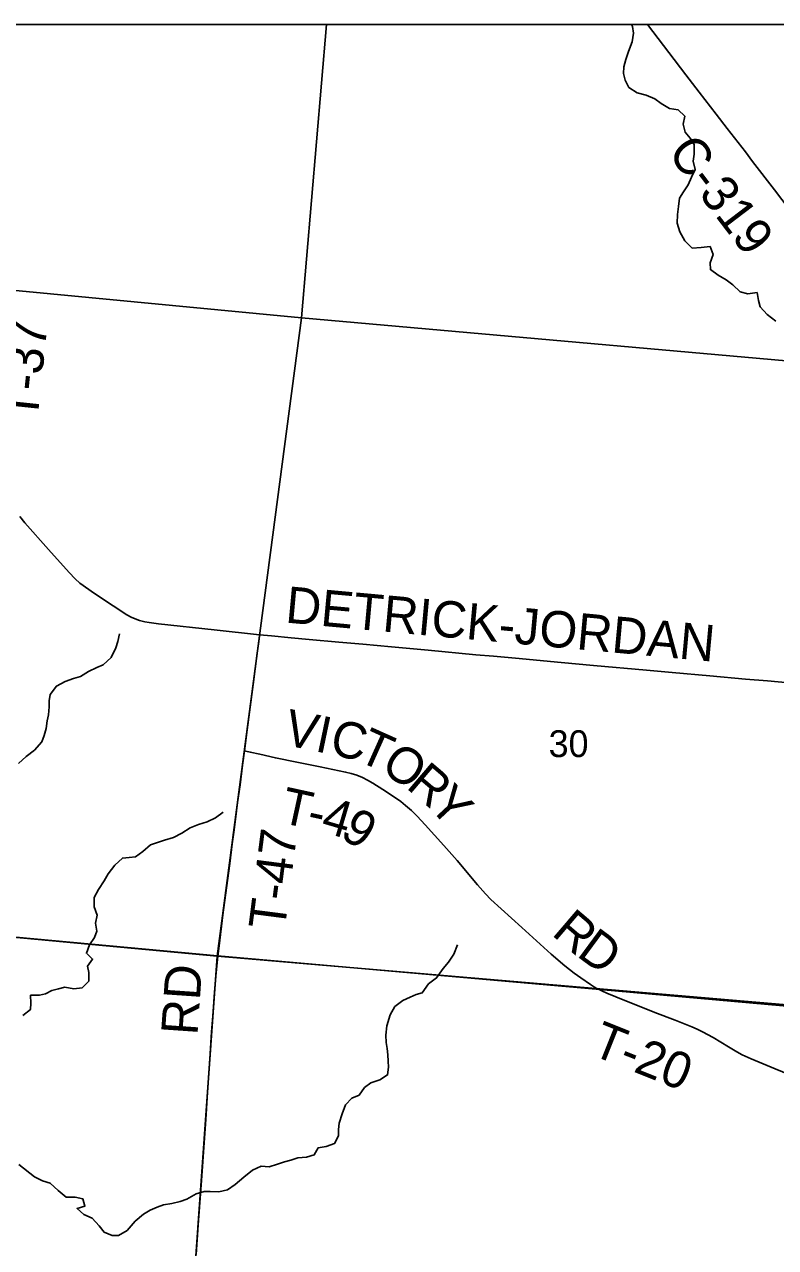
# Model space of a CAD drawing. Extents: x 0 to 34, y 0 to 22.
# Drawn here: x 3.909 to 5.08, y 18.991 to 20.9 of the extents above; entities that cross this region are included whole.
import ezdxf

# ---------------------------------------------------------------- set-up
doc = ezdxf.new("R2010")
doc.units = 0
for name, color, linetype in [('Default', 7, 'Continuous'), ('GM_X_City_Street', 7, 'Continuous'), ('GM_X_County_Road', 7, 'Continuous'), ('GM_X_County_Road_Text', 7, 'Continuous'), ('GM_X_Minor_River', 7, 'Continuous'), ('GM_X_Section', 7, 'Continuous'), ('GM_X_Section_Text', 7, 'Continuous'), ('GM_X_Township_Road', 7, 'Continuous'), ('GM_X_Township_Road_Text', 7, 'Continuous')]:
    doc.layers.add(name, color=color, linetype=linetype)

msp = doc.modelspace()

# ---------------------------------------------------------------- linework, layer by layer
at = {"layer": 'Default'}
for points in [[(4.3798, 20.9), (3.3925, 20.9), (3.3559, 20.5363), (4.3405, 20.4419)], [(5.3633, 20.9), (4.3798, 20.9), (4.3405, 20.4419), (5.3135, 20.3557)]]:
    msp.add_lwpolyline(points, close=True, dxfattribs=at)
at = {"layer": 'GM_X_City_Street'}
for points in [[(8.7795, 20.9), (3.3961, 20.9)], [(5.185, 18.9419), (5.1894, 18.9945), (5.1927, 19.0376), (5.1954, 19.0684), (5.2004, 19.1272), (5.2034, 19.1643), (5.2042, 19.1724), (5.2077, 19.2098), (5.2093, 19.2272), (5.2108, 19.2453), (5.2133, 19.2734), (5.2164, 19.3114), (5.2191, 19.3417), (5.2204, 19.3568), (4.8058, 19.3935), (4.2098, 19.4463), (3.2709, 19.533)], [(3.2709, 19.533), (4.2098, 19.4463), (4.8058, 19.3935), (5.2204, 19.3568), (5.9589, 19.2964), (6.8431, 19.2142)]]:
    msp.add_lwpolyline(points, dxfattribs=at)
at = {"layer": 'GM_X_County_Road'}
for points in [[(5.2974, 20.3579), (5.293, 20.3644), (5.2855, 20.3743), (5.2601, 20.4057), (5.2427, 20.4276), (5.2294, 20.4448), (5.2049, 20.4768), (5.1878, 20.4989), (5.1537, 20.5432), (5.1404, 20.5604), (5.1177, 20.5899), (5.1065, 20.6047), (5.0895, 20.627), (5.0782, 20.6418), (5.0442, 20.6861), (5.0329, 20.7009), (5.0045, 20.7378), (4.9874, 20.76), (4.9609, 20.7944), (4.9401, 20.8215), (4.9136, 20.856), (4.8967, 20.8782), (4.88, 20.9)], [(3.9011, 20.1318), (3.9091, 20.1223), (3.9462, 20.0804), (3.9782, 20.0446), (3.9878, 20.0346), (3.995, 20.0281), (3.9999, 20.0242), (4.0125, 20.0152), (4.027, 20.0056), (4.047, 19.9924), (4.0681, 19.9787), (4.0748, 19.975), (4.0813, 19.9721), (4.0877, 19.9697), (4.0963, 19.9676), (4.1031, 19.9663), (4.1177, 19.9644), (4.2042, 19.9551), (4.2753, 19.9475)], [(4.2753, 19.9475), (4.2937, 19.9455), (4.3247, 19.9425), (4.3525, 19.9399), (4.3989, 19.9359), (4.4361, 19.9328), (4.4807, 19.9284), (4.5381, 19.9233), (4.6124, 19.9163), (4.6402, 19.914), (4.6742, 19.9108), (4.7454, 19.9041), (4.7958, 19.8994), (4.8784, 19.892), (4.9186, 19.8883), (4.9774, 19.8831), (5.0331, 19.8781), (5.0672, 19.8753), (5.1228, 19.8701), (5.1909, 19.864), (5.231, 19.8603), (5.2642, 19.8573)]]:
    msp.add_lwpolyline(points, dxfattribs=at)
at = {"layer": 'GM_X_Minor_River'}
for points in [[(5.0802, 20.4367), (5.067, 20.4475), (5.0558, 20.4594), (5.0536, 20.4689), (5.0511, 20.4815), (5.0367, 20.4797), (5.0246, 20.4825), (5.0133, 20.4937), (5.0031, 20.5014), (4.9903, 20.5088), (4.9783, 20.5173), (4.978, 20.5279), (4.9827, 20.5411), (4.9779, 20.5533), (4.9639, 20.5516), (4.9498, 20.551), (4.9386, 20.5625), (4.9304, 20.5763), (4.9267, 20.5896), (4.9269, 20.6033), (4.9286, 20.6158), (4.9299, 20.6287), (4.9365, 20.6385), (4.9438, 20.6498), (4.9489, 20.6615), (4.9544, 20.6736), (4.9515, 20.6866), (4.9531, 20.6975), (4.9529, 20.7124), (4.9466, 20.7223), (4.9391, 20.7319), (4.9359, 20.7444), (4.9387, 20.7566), (4.9278, 20.7669), (4.9145, 20.7686), (4.9017, 20.7767), (4.8915, 20.7841), (4.8779, 20.7896), (4.8639, 20.7935), (4.8511, 20.8016), (4.8452, 20.8131), (4.843, 20.8234), (4.8431, 20.834), (4.8463, 20.8454), (4.8506, 20.8578), (4.8561, 20.873), (4.8586, 20.8866), (4.8568, 20.8969), (4.8553, 20.9)], [(3.899, 19.7467), (3.9113, 19.7576), (3.9243, 19.7673), (3.9355, 19.7804), (3.9394, 19.7903), (3.9422, 19.8009), (3.9439, 19.813), (3.9459, 19.8225), (3.9468, 19.835), (3.947, 19.8445), (3.9486, 19.8544), (3.9582, 19.8672), (3.972, 19.8746), (3.985, 19.879), (3.9957, 19.8823), (4.0083, 19.8898), (4.0213, 19.8961), (4.0312, 19.9005), (4.0435, 19.9121), (4.0509, 19.9269), (4.0541, 19.9367), (4.0569, 19.9488)], [(3.9058, 19.3533), (3.9177, 19.3623), (3.9186, 19.3726), (3.918, 19.3847), (3.9317, 19.3849), (3.9412, 19.3871), (3.9512, 19.3923), (3.9618, 19.3948), (3.9714, 19.3974), (3.9854, 19.3949), (3.9983, 19.3963), (4.0087, 19.4068), (4.0089, 19.4205), (4.0067, 19.43), (4.0148, 19.4413), (4.0051, 19.4502), (4.0098, 19.4634), (4.0179, 19.4751), (4.0215, 19.485), (4.0193, 19.4975), (4.0218, 19.51), (4.017, 19.523), (4.0172, 19.5371), (4.0242, 19.5499), (4.0327, 19.5631), (4.0389, 19.5744), (4.0493, 19.5876), (4.0613, 19.5989), (4.0719, 19.5995), (4.0814, 19.6009), (4.0933, 19.6091), (4.1048, 19.6196), (4.1144, 19.6226), (4.1269, 19.6266), (4.141, 19.631), (4.154, 19.6377), (4.1667, 19.6459), (4.18, 19.6511), (4.1934, 19.6555), (4.2064, 19.6618), (4.2183, 19.6704)], [(3.8999, 19.1204), (3.9243, 19.1011), (3.9364, 19.0953), (3.9485, 19.0913), (3.9609, 19.0798), (3.9737, 19.0697), (3.9874, 19.0696), (3.9995, 19.0672), (4.0028, 19.0557), (3.9905, 19.0517), (4.0011, 19.0428), (4.0143, 19.037), (4.0248, 19.0251), (4.0326, 19.0151), (4.0455, 19.01), (4.0554, 19.0099), (4.0687, 19.0177), (4.0811, 19.032), (4.0941, 19.0429), (4.1045, 19.0492), (4.1152, 19.054), (4.1251, 19.0577), (4.1384, 19.0598), (4.1514, 19.0627), (4.1617, 19.0664), (4.1762, 19.0746), (4.1888, 19.0782), (4.1983, 19.0785), (4.2116, 19.078), (4.2253, 19.0812), (4.2372, 19.0894), (4.2506, 19.1007), (4.2644, 19.1115), (4.2774, 19.1178), (4.2899, 19.1169), (4.3033, 19.121), (4.314, 19.125), (4.3239, 19.1272), (4.3349, 19.1309), (4.3482, 19.1322), (4.3604, 19.1355), (4.3667, 19.1468), (4.3792, 19.1486), (4.3922, 19.1534), (4.3984, 19.1655), (4.3982, 19.1753), (4.3994, 19.1852), (4.4038, 19.1996), (4.4093, 19.2136), (4.4189, 19.2241), (4.4304, 19.2286), (4.4389, 19.241), (4.4489, 19.2481), (4.4626, 19.2525), (4.4748, 19.2603), (4.4761, 19.2725), (4.4755, 19.282), (4.4752, 19.2915), (4.4742, 19.3014), (4.4724, 19.3109), (4.4722, 19.3227), (4.4735, 19.3371), (4.4791, 19.3542), (4.4861, 19.367), (4.4987, 19.3764), (4.5098, 19.3819), (4.5194, 19.386), (4.5289, 19.3886), (4.5389, 19.4025), (4.5512, 19.4119), (4.5613, 19.4266), (4.5701, 19.4363), (4.5783, 19.4488), (4.5841, 19.4635)]]:
    msp.add_lwpolyline(points, dxfattribs=at)
at = {"layer": 'GM_X_Section'}
for points in [[(3.3559, 20.5363), (4.3405, 20.4419), (4.2088, 19.4458), (3.2703, 19.5334)], [(4.3405, 20.4419), (5.3135, 20.3557), (5.2197, 19.3596), (4.2088, 19.4458)], [(3.2703, 19.5334), (4.2088, 19.4458), (4.1385, 18.4517), (3.1795, 18.5396)], [(4.2088, 19.4458), (5.2197, 19.3596), (5.133, 18.3597), (4.1385, 18.4517)]]:
    msp.add_lwpolyline(points, close=True, dxfattribs=at)
at = {"layer": 'GM_X_Township_Road'}
for points in [[(4.2516, 19.7661), (4.2558, 19.799), (4.265, 19.8696), (4.2716, 19.9188), (4.2739, 19.9369), (4.275, 19.9453), (4.2753, 19.9475)], [(4.21, 19.4457), (4.2119, 19.4621), (4.2179, 19.5104), (4.2286, 19.5902), (4.2326, 19.6209), (4.2349, 19.6393), (4.2381, 19.6639), (4.2409, 19.6854), (4.2447, 19.713), (4.2487, 19.7437), (4.2516, 19.7661)], [(4.2516, 19.7661), (4.2536, 19.7657), (4.2606, 19.7643), (4.2757, 19.7608), (4.2999, 19.7553), (4.3333, 19.7483), (4.3697, 19.7411), (4.4092, 19.733), (4.4182, 19.7309), (4.427, 19.7281), (4.4355, 19.7245), (4.4437, 19.7203), (4.4518, 19.7157), (4.4675, 19.7059), (4.4856, 19.6939), (4.4957, 19.6869), (4.5029, 19.6811), (4.5122, 19.6729), (4.521, 19.6642), (4.5337, 19.6507), (4.5626, 19.6184), (4.5832, 19.5952), (4.6151, 19.5572), (4.6274, 19.5432), (4.636, 19.5342), (4.6518, 19.5194), (4.6842, 19.4904), (4.7302, 19.4489), (4.7515, 19.4307), (4.7661, 19.4191), (4.7761, 19.4118), (4.7911, 19.4014), (4.7975, 19.3973), (4.8013, 19.3953), (4.806, 19.393)], [(4.1761, 18.9801), (4.1795, 19.0266), (4.184, 19.0886), (4.1856, 19.1104), (4.1882, 19.1476), (4.1912, 19.191), (4.1935, 19.2251), (4.1955, 19.2561), (4.198, 19.2933), (4.2003, 19.3274), (4.2021, 19.3522), (4.2047, 19.3894), (4.2073, 19.4204), (4.21, 19.4457)], [(4.806, 19.393), (4.8098, 19.3912), (4.8169, 19.3881), (4.8309, 19.3822), (4.8915, 19.358), (4.9234, 19.3457), (4.9494, 19.3357), (4.9579, 19.332), (4.9662, 19.3279), (4.9824, 19.3188), (5.0063, 19.3043), (5.0197, 19.2963), (5.028, 19.292), (5.0421, 19.2855), (5.0794, 19.27), (5.111, 19.2569)]]:
    msp.add_lwpolyline(points, dxfattribs=at)

# ---------------------------------------------------------------- texts
at = {"layer": 'GM_X_County_Road_Text'}
for s, height, rotation, p in [('C-319', 0.05682, 307.3054, (4.9102, 20.6997)), ('DETRICK-JORDAN', 0.056818, 354.7624, (4.3143, 19.9666))]:
    msp.add_text(s, height=height, rotation=rotation, dxfattribs=at).set_placement(p)
at = {"layer": 'GM_X_Section_Text'}
msp.add_text('30', height=0.04186, rotation=0, dxfattribs=at).set_placement((4.726, 19.7565))
at = {"layer": 'GM_X_Township_Road_Text'}
for s, height, rotation, p in [('T-37', 0.05682, 84.0115, (3.9286, 20.2808)), ('V', 0.0568, 348.1978, (4.3109, 19.7762)), ('I', 0.0568, 348.168, (4.3599, 19.766)), ('C', 0.0568, 347.2011, (4.3825, 19.7613)), ('T', 0.0568, 335.8965, (4.4252, 19.7519)), ('O', 0.0568, 326.5403, (4.4618, 19.7357)), ('R', 0.0568, 319.5778, (4.5021, 19.7092)), ('T', 0.0568, 347.6781, (4.3053, 19.6547)), ('Y', 0.0568, 313.1064, (4.5364, 19.6802)), ('4', 0.0568, 343.5435, (4.3686, 19.6409)), ('-', 0.0568, 347.6016, (4.3468, 19.6456)), ('9', 0.0568, 327.8573, (4.3984, 19.6326)), ('T-47', 0.05682, 82.6601, (4.3142, 19.4851)), ('R', 0.0568, 319.5088, (4.7291, 19.4799)), ('D', 0.0568, 323.5953, (4.768, 19.4469)), ('RD', 0.05682, 86.0508, (4.1782, 19.3214)), ('T-20', 0.05682, 338.2081, (4.79, 19.2927))]:
    msp.add_text(s, height=height, rotation=rotation, dxfattribs=at).set_placement(p)

doc.saveas('drawing.dxf')
